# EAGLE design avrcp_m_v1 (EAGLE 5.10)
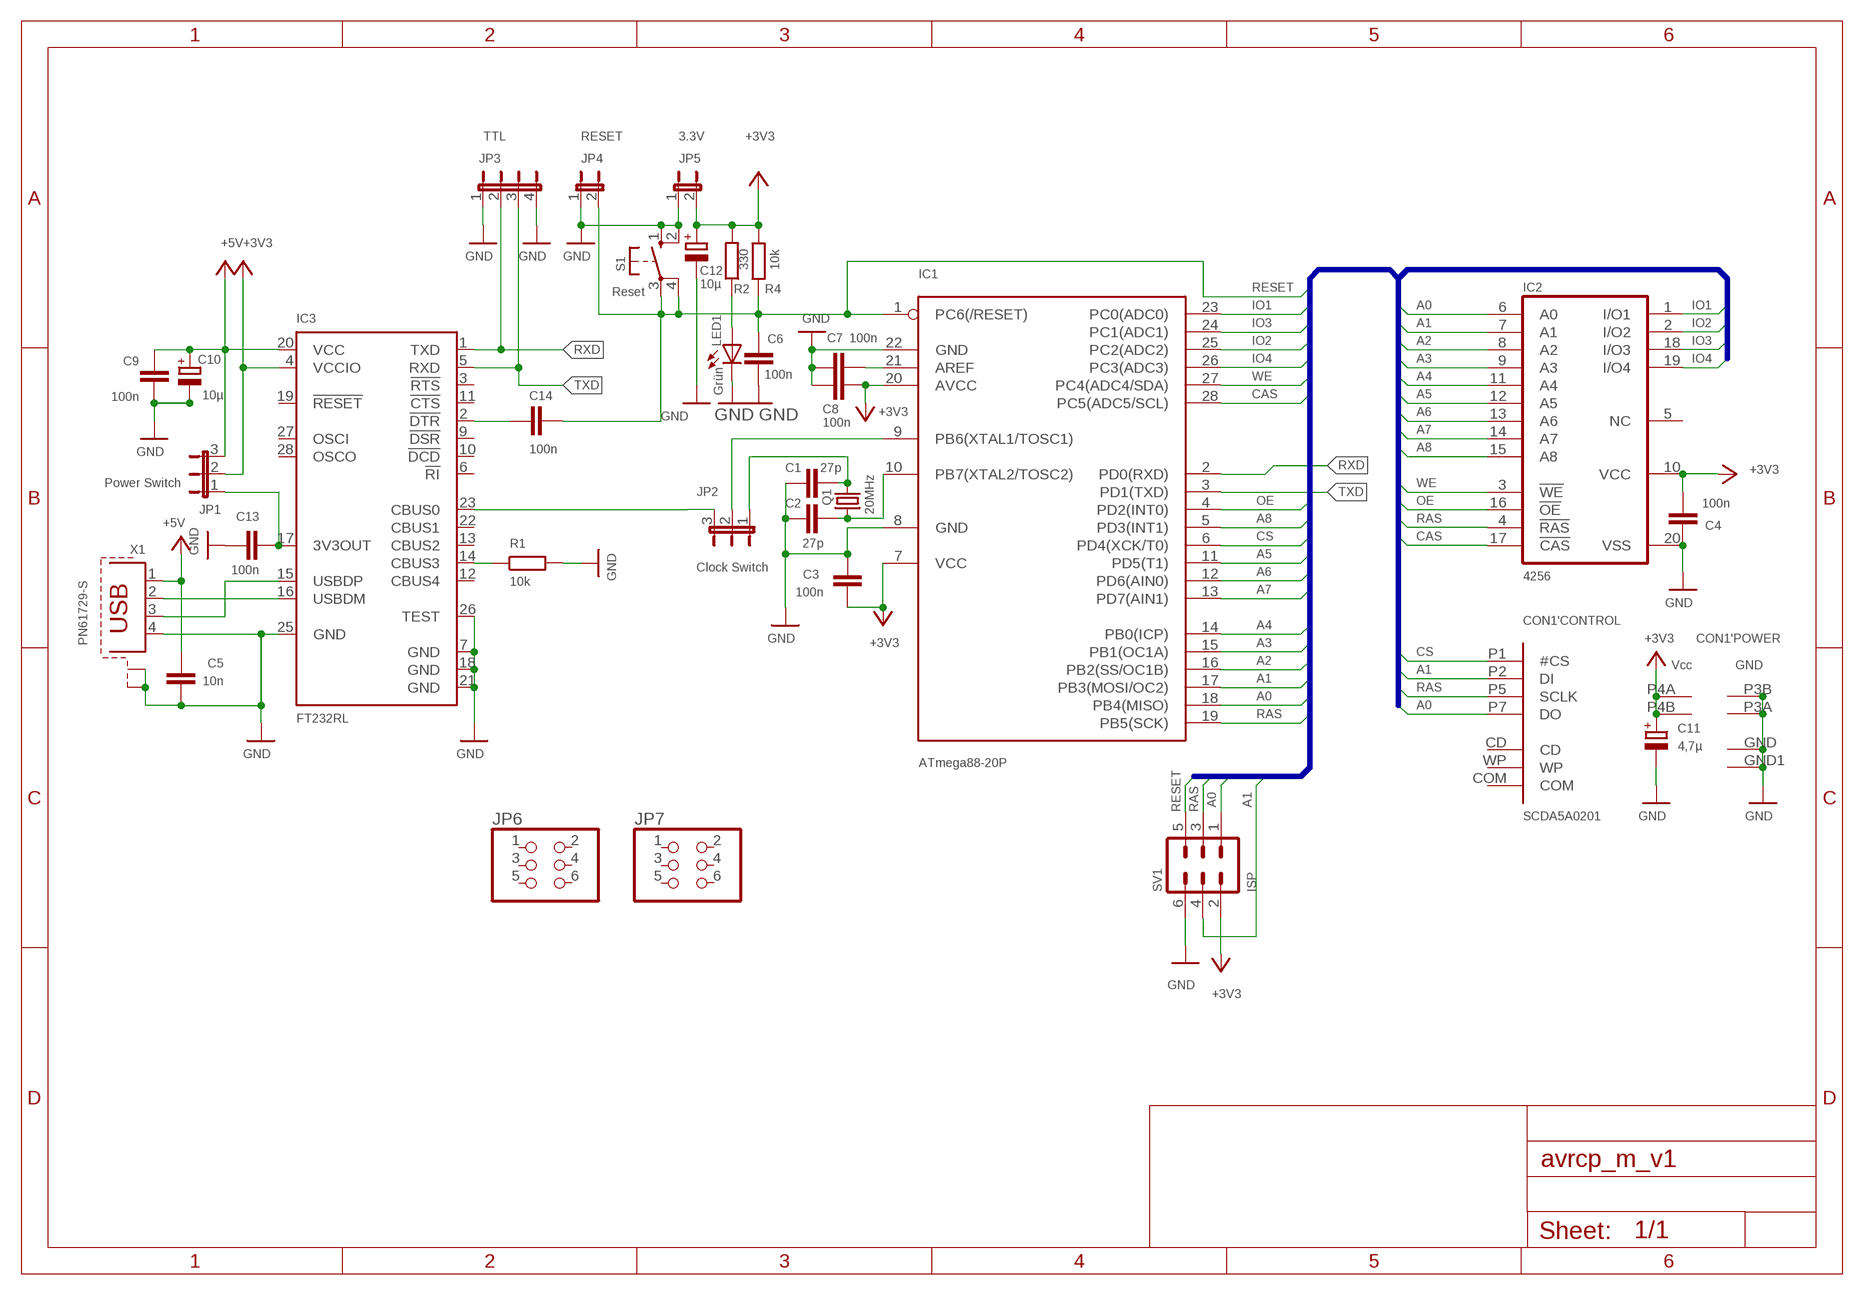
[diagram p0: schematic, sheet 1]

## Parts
C1  27p  C-EU025-024X044  [C025-024X044]
C2  27p  C-EU025-024X044  [C025-024X044]
C3  100n  C-EU025-024X044  [C025-024X044]
C4  100n  C-EU025-024X044  [C025-024X044]
C5  10n  C-EU025-024X044  [C025-024X044]
C6  100n  C-EU025-024X044  [C025-024X044]
C7  100n  C-EU025-024X044  [C025-024X044]
C8  100n  C-EU025-024X044  [C025-024X044]
C9  100n  C-EU025-024X044  [C025-024X044]
C10  10µ  CPOL-EUE2-5  [E2-5]
C11  4,7µ  CPOL-EUE2-4  [E2-4]
C12  10µ  CPOL-EUE2-4  [E2-4]
C13  100n  C-EU025-024X044  [C025-024X044]
C14  100n  C-EU025-024X044  [C025-024X044]
CON1  SCDA5A0201  [SCDA5A0201]
IC1  ATmega88-20P  MEGA8-P  [DIL28-3]
IC2  4256  514256ALP  [DIL20]
IC3  FT232RL  [SSOP28]
JP1  Power Switch  JP2E  [JP2]
JP2  Clock Switch  JP2E  [JP2]
JP3  TTL  JP4E  [JP4]
JP4  RESET  JP1E  [JP1]
JP5  3.3V  JP1E  [JP1]
JP6  PINHD-2X3  [2X03]
JP7  PINHD-2X3  [2X03]
LED1  Grün  LED3MM  [LED3MM]
Q1  20MHz  CRYSTALHC49U-V  [HC49U-V]
R1  10k  R-EU_0207/7  [0207/7]
R2  330  R-EU_0207/7  [0207/7]
R4  10k  R-EU_0207/7  [0207/7]
S1  Reset  10-XX  [B3F-10XX]
SV1  ISP  ML6  [ML6]
X1  PN61729-S  [PN61729-S]

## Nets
+3V3: C3.1 C4.2 C8.1 C11.+ C12.+ CON1.P4A('POWER:VCC) CON1.P4B('POWER:VCC1) IC1.7(VCC) IC1.20(AVCC) IC2.10(VCC) IC3.4(VCCIO) JP1.2 JP5.2 R2.2 R4.1 SV1.2
+5V: C5.2 C9.2 C10.+ IC3.20(VCC) JP1.3 X1.1
A0: CON1.P7('CONTROL:DO) IC1.18(PB4(MISO)) IC2.6(A0) SV1.1
A1: CON1.P2('CONTROL:DI) IC1.17(PB3(MOSI/OC2)) IC2.7(A1) SV1.4
A2: IC1.16(PB2(SS/OC1B)) IC2.8(A2)
A3: IC1.15(PB1(OC1A)) IC2.9(A3)
A4: IC1.14(PB0(ICP)) IC2.11(A4)
A5: IC1.11(PD5(T1)) IC2.12(A5)
A6: IC1.12(PD6(AIN0)) IC2.13(A6)
A7: IC1.13(PD7(AIN1)) IC2.14(A7)
A8: IC1.5(PD3(INT1)) IC2.15(A8)
CAS: IC1.28(PC5(ADC5/SCL)) IC2.17(!CAS)
CS: CON1.P1('CONTROL:#CS) IC1.6(PD4(XCK/T0))
GND: C1.1 C2.1 C3.2 C4.1 C5.1 C6.1 C7.2 C8.2 C9.1 C10.- C11.- C12.- C13.1 CON1.GND1('POWER:GND) CON1.GND('POWER:GND) CON1.P3A('POWER:GND) CON1.P3B('POWER:GND) IC1.8(GND) IC1.22(GND) IC2.20(VSS) IC3.7(GND) IC3.18(GND) IC3.21(GND) IC3.25(GND) IC3.26(TEST) JP3.1 JP3.4 JP4.1 JP5.1 LED1.K(C) R1.2 S1.1(S) S1.2(S1) SV1.6 X1.4 X1.S1 X1.S2
IO1: IC1.23(PC0(ADC0)) IC2.1(I/O1)
IO2: IC1.25(PC2(ADC2)) IC2.2(I/O2)
IO3: IC1.24(PC1(ADC1)) IC2.18(I/O3)
IO4: IC1.26(PC3(ADC3)) IC2.19(I/O4)
N$1: IC3.14(CBUS3) R1.1
N$2: C13.2 IC3.17(3V3OUT) JP1.1
N$3: C7.1 IC1.21(AREF)
N$4: IC1.9(PB6(XTAL1/TOSC1)) JP2.2
N$5: C2.2 IC1.10(PB7(XTAL2/TOSC2)) Q1.1
N$6: C1.2 JP2.1 Q1.2
N$7: LED1.A R2.1
N$8: IC3.23(CBUS0) JP2.3
N$9: IC3.16(USBDM) X1.2
N$10: IC3.15(USBDP) X1.3
N$11: C14.2 IC3.2(!DTR)
OE: IC1.4(PD2(INT0)) IC2.16(!OE)
RAS: CON1.P5('CONTROL:SCLK) IC1.19(PB5(SCK)) IC2.4(!RAS) SV1.3
RESET: C6.2 C14.1 IC1.1(PC6(/RESET)) JP4.2 R4.2 S1.3(P) S1.4(P1) SV1.5
RXD: IC1.2(PD0(RXD)) IC3.1(TXD) JP3.2
TXD: IC1.3(PD1(TXD)) IC3.5(RXD) JP3.3
WE: IC1.27(PC4(ADC4/SDA)) IC2.3(!WE)
Unconnected: CON1.CD('CONTROL:CD) CON1.COM('CONTROL:COM) CON1.WP('CONTROL:WP) IC2.5(NC) IC3.3(!RTS) IC3.6(!RI) IC3.9(!DSR) IC3.10(!DCD) IC3.11(!CTS) IC3.12(CBUS4) IC3.13(CBUS2) IC3.19(!RESET) IC3.22(CBUS1) IC3.27(OSCI) IC3.28(OSCO) JP6.1 JP6.2 JP6.3 JP6.4 JP6.5 JP6.6 JP7.1 JP7.2 JP7.3 JP7.4 JP7.5 JP7.6

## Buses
A[0..8],WE,OE,RAS,CAS,IO[1..4],RESET,CS

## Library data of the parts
C1-C9 C13 C14 = rcl:C-EU: CAPACITOR, European symbol
C10-C12 = rcl:CPOL-EU: POLARIZED CAPACITOR, European symbol
CON1 = SCDA5A0201:SCDA5A0201: ALPS Connector for SDMemory Card SD-CARD SCDA5A0201 SPI -MODE
IC1 = atmel:MEGA8-P: MICROCONTROLLER 8 Kbytes FLASH, 1 kbytes SRAM, 512 bytes EEPROM, USART, 4-channel 10 bit ADC, 2-channel 8 bit ADC Pin compatible with Atmega48, ATMega88, ATMega168 Source: avr.lbr
IC2 = memory-hitachi:514256ALP: MEMORY
IC3 = ftdichip:FT232R: Source: http://www.ftdichip.com/Documents/DataSheets/DS_FT232R_v104.pdf
JP1 JP2 = jumper:JP2E: JUMPER
JP3 = jumper:JP4E: JUMPER
JP4 JP5 = jumper:JP1E: JUMPER
JP6 JP7 = pinhead:PINHD-2X3: PIN HEADER
LED1 = led:LED: LED
Q1 = crystal:CRYSTAL: CRYSTAL
R1 R2 R4 = rcl:R-EU_: RESISTOR, European symbol
S1 = switch-omron:10-XX: OMRON SWITCH
SV1 = con-harting-ml:ML6: HARTING
X1 = con-berg:PN61729-S: BERG USB connector

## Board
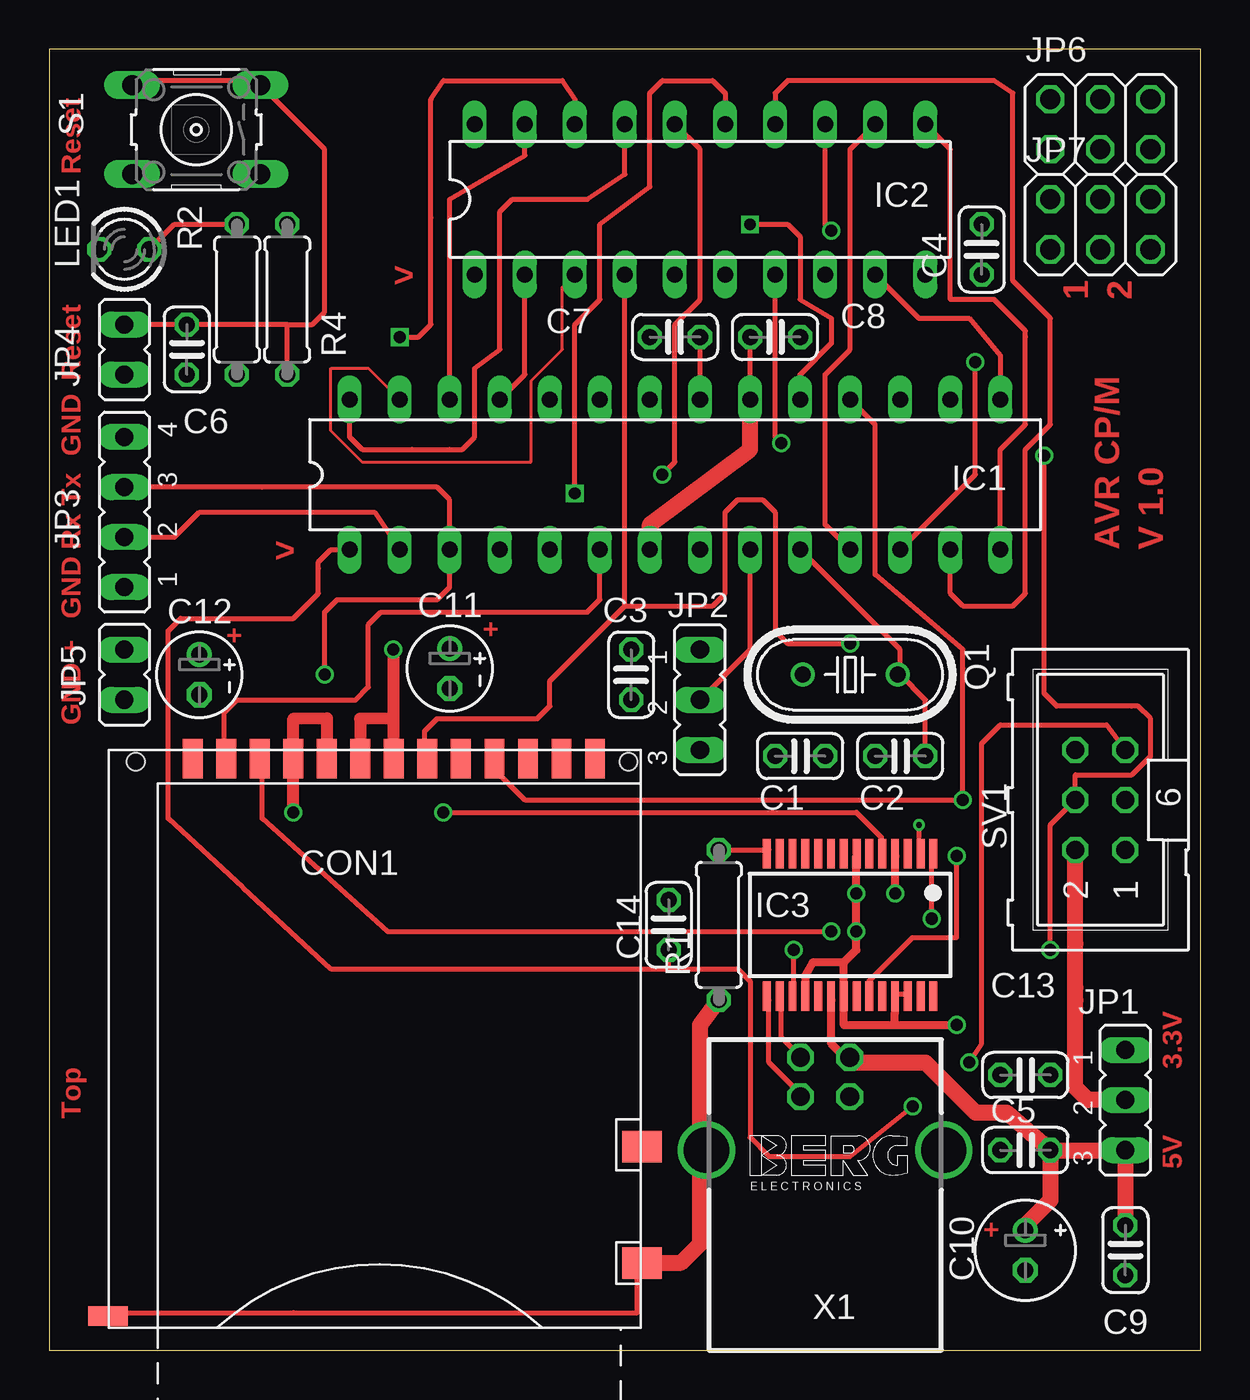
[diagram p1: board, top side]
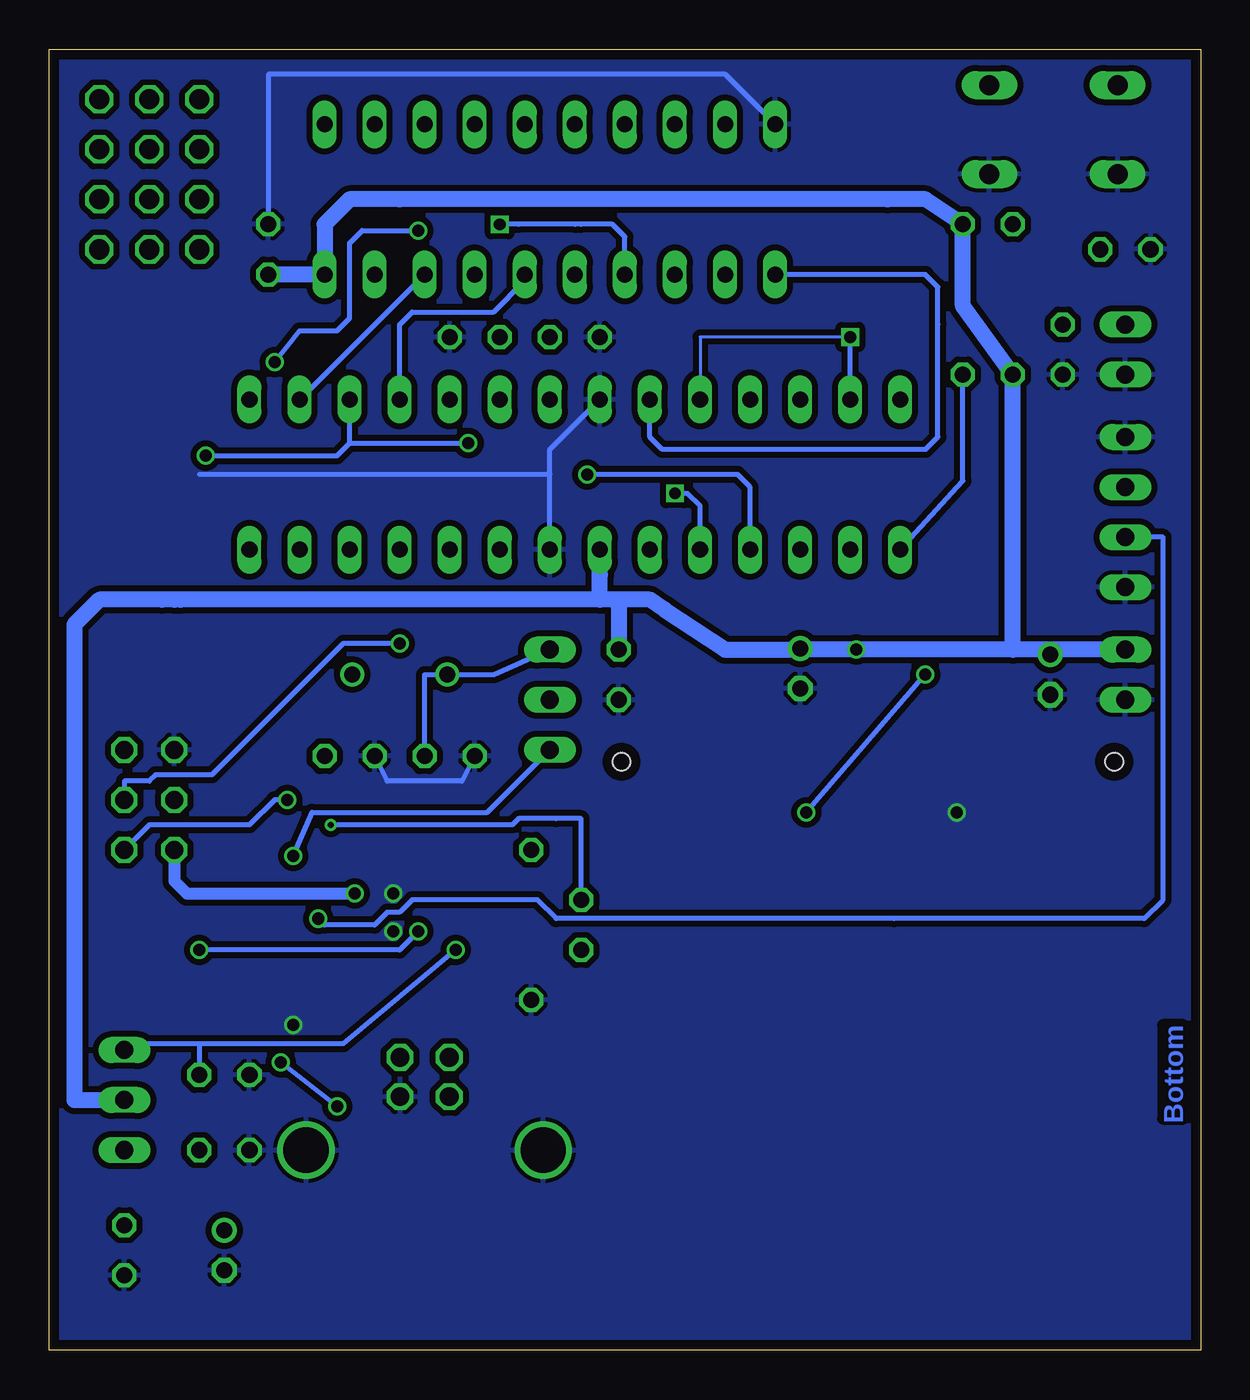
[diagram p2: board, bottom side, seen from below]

Size 58.42 x 66.04 mm. Coordinates in mm from the lower left corner, seen from the top.
Outline: 58.42,66.04 0,66.03 0,0 58.42,0 58.42,66.04
Copper layers (1*16): Top 0.035mm / dielectric 1.5mm / Bottom 0.035mm
Design rules "Eagle-DRU - 1109 - LeitOn - 01 and 02 layers": minimum track width 6mil, minimum drill 0.3mm, track to track 6mil, track to pad 6mil, pad to pad 6mil, via to via 6mil, smd to smd 6mil, copper to edge 20mil, drill to drill 10mil, minimum pad ring 8mil, minimum via ring 6mil, stop-mask expansion 3mil, vias tented up to drill 0mil, thermal gap 8mil

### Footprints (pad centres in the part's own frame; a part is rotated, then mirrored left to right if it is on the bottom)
C025-024X044 = drill 0.813 octagon: 1 -1.27,0; 2 1.27,0
E2-5 = drill 0.813 pad 1.27 round: + -1.016,0 | drill 0.813 pad 1.27 octagon: - 1.016,0
E2-4 = drill 0.813 pad 1.27 round: + -1.016,0 | drill 0.813 pad 1.27 octagon: - 1.016,0
SCDA5A0201 = smd 1 x 2: CD 9.475,-0.45; COM 11.175,-0.45; P1 -7.525,-0.45; P2 -5.825,-0.45; P3A -4.125,-0.45; P3B -2.425,-0.45; P4A -0.725,-0.45; P4B 0.975,-0.45; P5 2.675,-0.45; P6 4.375,-0.45; P7 6.075,-0.45; P8 7.775,-0.45; P9 -9.225,-0.45 | smd 2 x 1.6: GND 13.575,-26.05; WP 13.575,-20.15 | smd 2 x 1: GND1 -13.525,-28.75 | hole 0.9: -12.125,-0.6; 12.875,-0.6
DIL28-3 = drill 0.813 long: 1 -16.51,-3.81; 2 -13.97,-3.81; 3 -11.43,-3.81; 4 -8.89,-3.81; 5 -6.35,-3.81; 6 -3.81,-3.81; 7 -1.27,-3.81; 8 1.27,-3.81; 9 3.81,-3.81; 10 6.35,-3.81; 11 8.89,-3.81; 12 11.43,-3.81; 13 13.97,-3.81; 14 16.51,-3.81; 15 16.51,3.81; 16 13.97,3.81; 17 11.43,3.81; 18 8.89,3.81; 19 6.35,3.81; 20 3.81,3.81; 21 1.27,3.81; 22 -1.27,3.81; 23 -3.81,3.81; 24 -6.35,3.81; 25 -8.89,3.81; 26 -11.43,3.81; 27 -13.97,3.81; 28 -16.51,3.81
DIL20 = drill 0.813 long: 1 -11.43,-3.81; 2 -8.89,-3.81; 3 -6.35,-3.81; 4 -3.81,-3.81; 5 -1.27,-3.81; 6 1.27,-3.81; 7 3.81,-3.81; 8 6.35,-3.81; 9 8.89,-3.81; 10 11.43,-3.81; 11 11.43,3.81; 12 8.89,3.81; 13 6.35,3.81; 14 3.81,3.81; 15 1.27,3.81; 16 -1.27,3.81; 17 -3.81,3.81; 18 -6.35,3.81; 19 -8.89,3.81; 20 -11.43,3.81
SSOP28 = smd 0.4 x 1.5: 1 -4.225,-3.625; 2 -3.575,-3.625; 3 -2.925,-3.625; 4 -2.275,-3.625; 5 -1.625,-3.625; 6 -0.975,-3.625; 7 -0.325,-3.625; 8 0.325,-3.625; 9 0.975,-3.625; 10 1.625,-3.625; 11 2.275,-3.625; 12 2.925,-3.625; 13 3.575,-3.625; 14 4.225,-3.625; 15 4.225,3.625; 16 3.575,3.625; 17 2.925,3.625; 18 2.275,3.625; 19 1.625,3.625; 20 0.975,3.625; 21 0.325,3.625; 22 -0.325,3.625; 23 -0.975,3.625; 24 -1.625,3.625; 25 -2.275,3.625; 26 -2.925,3.625; 27 -3.575,3.625; 28 -4.225,3.625
JP2 = drill 0.914 long: 1 -2.54,0; 2 0,0; 3 2.54,0
JP4 = drill 0.914 long: 1 -3.81,0; 2 -1.27,0; 3 1.27,0; 4 3.81,0
JP1 = drill 0.914 long: 1 0,-1.27; 2 0,1.27
2X03 = drill 1.016 octagon: 1 -2.54,-1.27; 2 -2.54,1.27; 3 0,-1.27; 4 0,1.27; 5 2.54,-1.27; 6 2.54,1.27
LED3MM = drill 0.813 octagon: A -1.27,0; K 1.27,0
HC49U-V = drill 0.813 round: 1 -2.413,0; 2 2.413,0
0207/7 = drill 0.813 octagon: 1 -3.81,0; 2 3.81,0
B3F-10XX = drill 1.016 long: 1 -3.251,2.261; 2 3.251,2.261; 3 -3.251,-2.261; 4 3.251,-2.261
ML6 = drill 0.914 octagon: 1 -2.54,-1.27; 2 -2.54,1.27; 3 0,-1.27; 4 0,1.27; 5 2.54,-1.27; 6 2.54,1.27
PN61729-S = drill 0.95 octagon: 1 1.25,4.71; 2 -1.25,4.71; 3 -1.25,2.71; 4 1.25,2.71 | drill 2.3 pad 2.9 round: S1 -6.02,0; S2 6.02,0

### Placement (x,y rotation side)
C1  38.1,30.16 0 top
C2  43.18,30.16 0 top
C3  29.53,34.29 270 top
C4  47.31,55.88 270 top
C5  49.53,10.16 0 top
C6  6.99,50.8 90 top
C7  31.75,51.44 180 top
C8  36.83,51.44 0 top
C9  54.61,5.08 90 top
C10  49.53,5.08 270 top
C11  20.32,34.61 270 top
C12  7.62,34.29 270 top
C13  49.53,13.97 0 top
C14  31.43,21.59 90 top
CON1  16.51,30.48 0 top
IC1  31.75,44.45 0 top
IC2  33.02,58.42 0 top
IC3  40.64,21.59 180 top
JP1  54.61,12.7 270 top
JP2  33.02,33.02 270 top
JP3  3.81,42.55 90 top
JP4  3.81,50.8 0 top
JP5  3.81,34.29 0 top
JP6  53.34,62.23 0 top
JP7  53.34,57.15 0 top
LED1  3.81,55.88 180 top
Q1  40.64,34.29 180 top
R1  33.97,21.59 270 top
R2  9.53,53.34 270 top
R4  12.06,53.34 270 top
S1  7.46,61.96 180 top
SV1  53.34,27.94 90 top
X1  39.37,10.16 0 top

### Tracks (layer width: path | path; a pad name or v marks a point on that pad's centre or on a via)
+3V3  (via drill 0.61)
  Top 0.254: 17.46,30.48 CON1.P4B 17.46,32.07 | 42.93,25.08 IC3.4 | 35.24,48.58 IC1.20 35.56,48.58 C8.1
  Top 0.406: v42.93,23.18 42.93,25.08
  Top 0.61: v17.46,35.56 17.46,32.07 | 17.46,32.07 17.46,30.48 | 17.46,32.07 15.77,32.05 CON1.P4A
  Top 0.813: JP1.2 52.7,12.7 52.07,13.34 52.07,17.14 52.07,17.78 52.07,18.41 52.07,20.64 SV1.2 | IC1.7 30.48,41.91 35.56,45.72 IC1.20
  Bottom 0.254: C12.+ 9.53,35.56 7.62,35.56 | 20.32,35.56 C11.+ | 27.21,37.61 27.3,37.47 | 52.39,38.1 52.07,38.1 51.75,38.1 | 29.53,38.1 29.53,37.78 | 52.7,38.1 55.88,38.1 52.7,38.1
  Bottom 0.305: 52.7,38.1 55.88,38.1 | 27.94,38.1 24.13,35.56 9.53,35.56
  Bottom 0.61: v42.93,23.18 50.48,23.18 51.44,23.18 52.07,23.81 SV1.2
  Bottom 0.813: JP5.2 7.62,35.56 9.53,35.56 | 9.53,35.56 v17.46,35.56 20.32,35.56 24.13,35.56 27.21,37.61 27.94,38.1 | 27.94,38.1 29.53,38.1 | 29.53,38.1 30.48,38.1 30.48,39.37 IC1.7 | 27.94,38.1 29.53,38.1 | 29.53,38.1 51.75,38.1 | 51.75,38.1 52.07,38.1 | JP1.2 57.15,12.7 57.15,36.83 55.88,38.1 52.7,38.1 52.07,38.1 | C4.2 IC2.10 44.45,57.15 43.18,58.42 40.64,58.42 15.88,58.42 13.97,58.42 R4.1 12.06,53.02 R2.2 9.53,35.56 | 29.53,37.78 C3.1 | 51.75,38.1 52.07,38.1
+5V
  Top 0.254: 49.53,6.35 C10.+ | 39.69,17.78 IC3.20 | X1.1 40.32,14.92
  Top 0.406: 39.69,17.78 39.69,15.56 40.32,14.92
  Top 0.813: C9.2 JP1.3 C5.2 | 49.53,6.35 50.8,7.62 C5.2 | C5.2 48.58,12.06 47.62,12.06 46.99,12.06 45.72,13.34 44.45,14.61 40.88,14.61 X1.1
A0  (via drill 0.61)
  Top 0.254: IC1.18 41.91,46.99 41.91,39.37 46.35,35.56 46.35,34.61 v46.35,27.94 24.13,27.94 22.86,29.21 CON1.P7
  Bottom 0.254: IC2.6 34.29,54.29 35.88,52.7 40.01,52.7 40.64,52.07 IC1.18 | SV1.1 53.34,26.67 48.26,26.67 46.99,27.94 v46.35,27.94
A1  (via drill 0.61)
  Top 0.254: v37.15,46.04 36.83,46.35 IC2.7 | v39.69,21.27 17.14,21.27 10.79,26.99 10.79,29.21 10.79,29.84 CON1.P2 | v50.8,20.32 50.8,26.67 SV1.4 52.07,29.21 54.93,29.21 55.88,30.16 55.88,32.07 55.24,32.7 54.93,32.7 51.12,32.7 50.48,33.34 v50.48,45.4
  Bottom 0.254: 43.18,46.04 IC1.17 | 43.18,46.04 v37.15,46.04 | v39.69,21.27 40.64,20.32 v50.8,20.32 | 43.18,46.04 43.81,45.4 v50.48,45.4
A2
  Bottom 0.254: IC2.8 41.91,52.07 IC1.16
A3
  Top 0.254: IC2.9 44.13,52.39 46.67,52.39 48.26,50.48 IC1.15
A4
  Top 0.254: IC1.14 48.26,45.72 49.53,46.99 49.53,51.44 49.53,51.75 47.94,53.34 45.72,53.34 45.72,60.96 IC2.11
A5
  Top 0.254: IC1.11 39.37,41.91 39.37,49.53 40.64,50.8 40.64,60.96 IC2.12
A6  (via drill 0.61)
  Top 0.254: IC1.12 46.99,44.45 v46.99,50.16 | v39.69,56.83 39.37,57.15 IC2.13
  Bottom 0.254: v46.99,50.16 45.72,51.75 45.09,51.75 44.13,51.75 43.81,51.75 43.18,52.39 43.18,56.2 42.55,56.83 v39.69,56.83
A7
  Top 0.254: IC1.13 45.72,38.42 46.35,37.78 48.9,37.78 49.53,38.42 49.53,45.72 50.8,46.99 50.8,52.39 48.9,54.29 48.9,63.82 47.94,64.45 37.47,64.45 36.83,63.82 IC2.14
A8  (via drill 0.6)
  Top 0.254: v26.67,43.5 26.67,52.07 27.94,53.34 27.94,57.15 30.48,59.05 30.48,63.82 31.11,64.45 33.66,64.45 34.29,63.82 IC2.15
  Bottom 0.254: IC1.5 25.4,42.86 26.04,43.5 v26.67,43.5
CAS
  Top 0.254: IC2.17 29.21,59.69 27.3,58.42 23.5,58.42 22.86,57.78 22.86,50.8 21.59,49.85 21.59,46.35 20.95,45.72 20.32,45.72 18.41,45.72 15.88,45.72 15.24,46.35 IC1.28
CS
  Top 0.254: IC1.6 27.94,38.1 27.3,37.47 16.83,37.47 16.19,36.83 16.19,33.66 15.56,33.02 9.53,33.02 8.89,32.38 8.89,30.16 CON1.P1
GND  (via drill 0.61)
  Top 0.254: IC3.26 43.5,18.1 42.86,18.1 IC3.25 42.86,17.78 42.91,17.14 | 38.37,18.09 IC3.18 | 40.32,18.1 IC3.21 40.32,17.78 | 40.96,25.08 IC3.7 | CON1.GND1 3.17,1.91 12.38,1.91 29.84,1.91 29.84,4.13 CON1.GND | C10.- 49.53,3.81 C10.- | 33.02,16.51 X1.S1 33.02,16.51
  Top 0.406: 38.37,18.09 38.37,19.04 38.73,19.68 40.32,19.68 | 40.32,18.1 40.32,19.68 | 40.96,25.08 v40.96,23.18 v40.96,21.27 40.96,20.32 40.32,19.68 | 42.91,16.51 42.91,17.14 | 42.91,16.51 40.32,16.51 40.32,17.78 | 42.91,16.51 v46.04,16.51 42.91,16.51
  Top 0.61: v12.38,27.3 CON1.P3A 12.38,32.07 14.09,32.08 CON1.P3B
  Top 0.813: R1.2 33.02,16.51 33.02,6.99 33.02,5.71 33.02,5.4 32.07,4.45 CON1.GND
  Bottom 0.254: C1.1 37.47,28.89 41.27,28.89 C2.1 | 33.02,44.45 33.02,45.72 IC1.22 | IC1.8 33.02,44.45 | 33.02,44.45 50.8,44.45 | X1.4 40.64,12.7 | C4.1 47.31,64.77 24.13,64.77 IC2.20
  pour Bottom (isolate 0.305): 0,66.04 58.42,66.04 58.42,0 0,0
IO1
  Bottom 0.254: IC2.1 13.97,54.61 13.34,53.98 13.34,52.07 13.34,46.35 13.97,45.72 27.3,45.72 27.94,46.35 IC1.23
IO2
  Top 0.254: IC1.25 24.13,49.53 IC2.2
IO3  (via drill 0.6)
  Top 0.254: IC2.18 26.67,63.5 26.04,64.45 20,64.45 19.37,63.5 19.37,57.47 19.37,52.07 18.73,51.44 v17.78,51.44
  Bottom 0.152: IC1.24 25.4,51.44 v17.78,51.44
  Bottom 0.254: 17.78,48.58 v17.78,51.44
IO4
  Top 0.254: IC1.26 20.32,49.53 20.32,58.42 24.13,60.64 IC2.19
N$1
  Top 0.254: R1.1 36.51,25.4 IC3.14
N$2  (via drill 0.61)
  Top 0.254: v37.78,20.32 37.78,18.1 IC3.17
  Bottom 0.254: 50.8,15.56 C13.2 | 50.8,15.56 53.98,15.56 JP1.1 | v37.78,20.32 43.5,15.56 50.8,15.56
N$3
  Top 0.254: IC1.21 C7.1
N$4
  Top 0.254: IC1.9 35.56,35.56 JP2.2
N$5
  Top 0.254: C2.2 44.45,33.02 43.18,34.29 | 43.18,34.29 Q1.1 43.18,34.29 | IC1.10 43.18,35.56 43.18,34.29
N$6
  Bottom 0.254: C1.2 39.37,34.29 Q1.2 | Q1.2 38.1,34.29 | Q1.2 38.1,34.29 | JP2.1 35.88,34.29 38.1,34.29 | Q1.2 38.1,34.29
N$7
  Top 0.254: LED1.A 6.35,57.15 R2.1
N$8  (via drill 0.61)
  Top 0.254: v46.04,25.08 46.04,20.95 43.81,20.95 41.59,18.73 41.59,18.1 IC3.23
  Bottom 0.254: v46.04,25.08 45.09,27.3 36.2,27.3 JP2.3
N$9
  Top 0.254: IC3.16 37.15,17.78 37.15,15.88 38.1,14.92 X1.2
N$10
  Top 0.254: IC3.15 36.51,17.78 36.51,14.61 38.1,13.02 X1.3
N$11  (via drill 0.3)
  Top 0.152: 44.13,26.04 44.13,25.4 IC3.2
  Top 0.254: v44.13,26.67 44.13,26.04
  Bottom 0.254: v44.13,26.67 42.23,26.67 34.92,26.67 34.61,26.99 32.7,26.99 31.43,26.99 C14.2
OE  (via drill 0.61)
  Top 0.254: v31.11,44.45 31.75,45.09 31.75,52.07 33.02,53.34 33.02,60.96 IC2.16
  Bottom 0.254: IC1.4 22.86,43.81 23.5,44.45 v31.11,44.45
RAS  (via drill 0.6, 0.61)
  Top 0.254: 29.21,37.78 IC2.4 | CON1.P5 19.05,30.48 19.05,31.43 19.68,32.07 23.81,32.07 24.77,32.07 25.4,32.7 25.4,33.97 26.67,35.24 29.21,37.78 | 29.21,37.78 33.66,37.78 34.29,38.42 34.29,42.55 34.92,43.18 36.2,43.18 36.83,42.55 36.83,36.51 37.47,35.88 v40.64,35.88 | IC1.19 38.1,49.53 39.69,51.12 39.69,52.39 38.1,53.34 38.1,56.52 37.47,57.15 v35.56,57.15
  Bottom 0.254: SV1.3 54.61,28.89 53.34,28.89 53.02,29.21 50.16,29.21 43.5,35.88 v40.64,35.88 | IC2.4 29.21,56.52 29.84,57.15 31.43,57.15 31.75,57.15 34.61,57.15 | 34.61,57.15 v35.56,57.15 34.61,57.15
RESET  (via drill 0.61)
  Top 0.152: 9.84,23.5 9.83,23.48
  Top 0.254: S1.4 4.45,64.45 10.48,64.45 S1.3 10.79,64.14 13.97,60.96 13.97,52.7 13.34,52.07 12.06,52.07 | JP4.2 C6.2 8.57,52.07 12.06,52.07 | R4.2 12.06,52.07 | 31.43,19.37 14.29,19.37 9.83,23.48 6.03,26.99 6.03,35.88 6.03,36.51 6.67,37.15 12.38,37.15 13.65,38.42 13.65,39.69 13.65,40.01 14.29,40.64 IC1.1 | 31.43,19.37 34.92,19.37 35.56,18.73 35.56,10.79 36.51,9.84 40.64,9.84 v43.81,12.38 | v46.67,14.61 47.31,15.56 47.31,30.8 48.26,31.75 53.66,31.75 SV1.5 | 31.43,19.37 C14.1
  Bottom 0.254: IC1.1 12.06,44.13 R4.2 | v43.81,12.38 v46.67,14.61
RXD  (via drill 0.61)
  Top 0.254: v44.77,21.91 44.77,25.08 IC3.1 | IC1.2 16.51,42.55 7.62,42.55 6.35,41.27 JP3.2
  Bottom 0.254: 1.91,37.47 1.91,38.1 | 1.91,37.47 1.91,38.1 | 1.91,38.1 1.91,41.27 JP3.2 | 1.91,37.47 1.91,32.7 1.91,22.86 2.86,21.91 15.56,21.91 32.7,21.91 33.66,22.86 40.01,22.86 40.64,22.23 41.27,22.23 41.91,21.59 44.45,21.59 v44.77,21.91 | 1.91,37.47 1.91,38.1
TXD  (via drill 0.61)
  Top 0.254: IC3.5 42.23,25.4 42.23,26.04 40.96,27.3 v20,27.3 | v13.97,34.29 13.97,37.47 14.61,38.1 19.68,38.1 20.32,38.73 | 20.32,38.73 IC1.3 | 20.32,38.73 20.32,43.18 19.68,43.81 10.79,43.81 JP3.3
  Bottom 0.254: v20,27.3 v13.97,34.29
WE
  Top 0.152: IC1.27 16.19,49.85 14.29,49.85 14.29,46.67 15.88,45.09 24.45,45.09 24.45,49.21 26.04,50.8 26.04,53.98 IC2.3

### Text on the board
Top: Reset | > | 1 | 2 | Reset | GND | Tx | Rx | AVR CP/M | V 1.0 | > | GND | + | + | + | GND | 3.3V | Top | 5V | +
Bottom: Bottom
